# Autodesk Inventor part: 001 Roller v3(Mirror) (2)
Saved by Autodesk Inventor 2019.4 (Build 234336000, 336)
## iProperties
Created: 2020-06
Part Number: 001 Roller v3(Mirror) (2)
Material: Generic
Document SubType Name: Modeling
Designer: Administrator
Density: 1 g/cm^3
Appearance: Default
Title: 001 Roller v3(Mirror) (2)
Author: Administrator
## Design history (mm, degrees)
